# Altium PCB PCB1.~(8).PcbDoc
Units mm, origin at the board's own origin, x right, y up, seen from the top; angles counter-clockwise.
Board outline 200.03 x 149.86 mm, 2 copper layers (Top Layer, Bottom Layer); 48 components, 42 nets, 243 pads, 0 vias.
Unrouted connection lines stored in the file: 177.
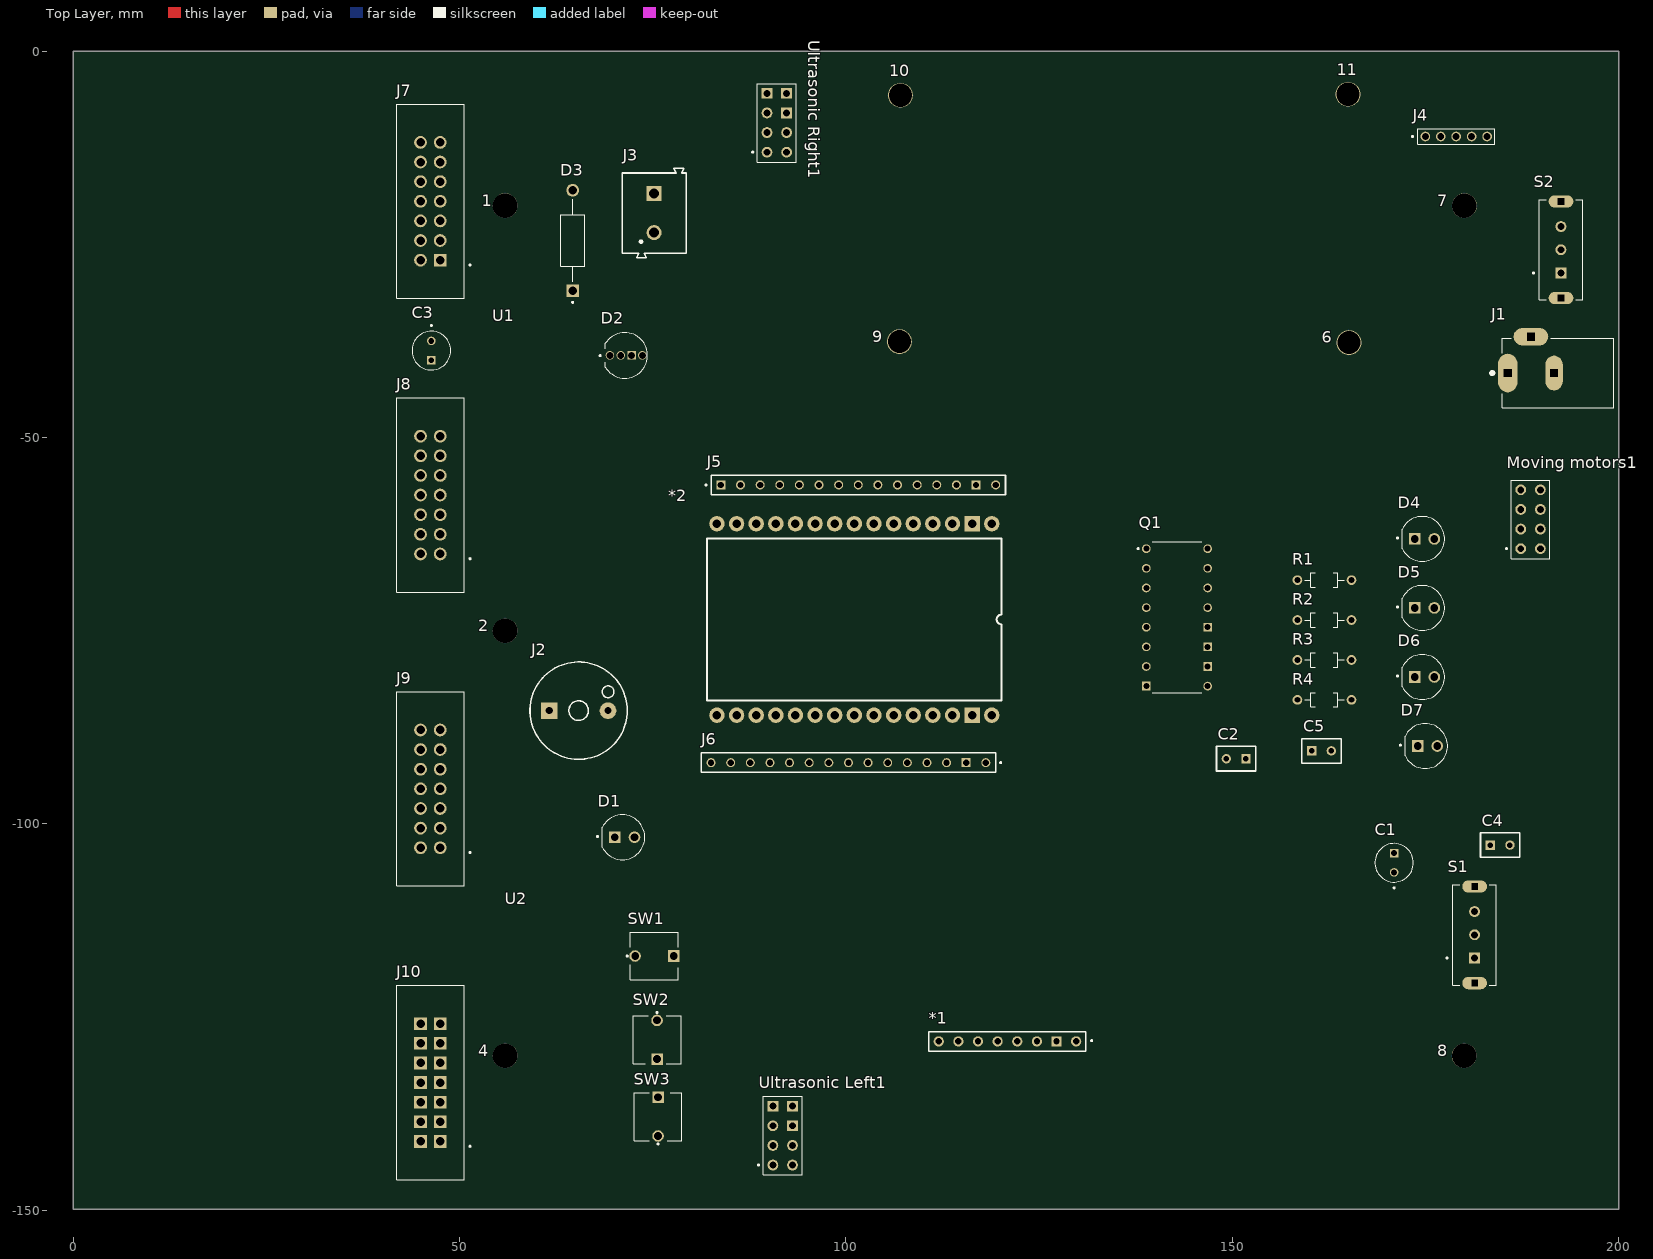
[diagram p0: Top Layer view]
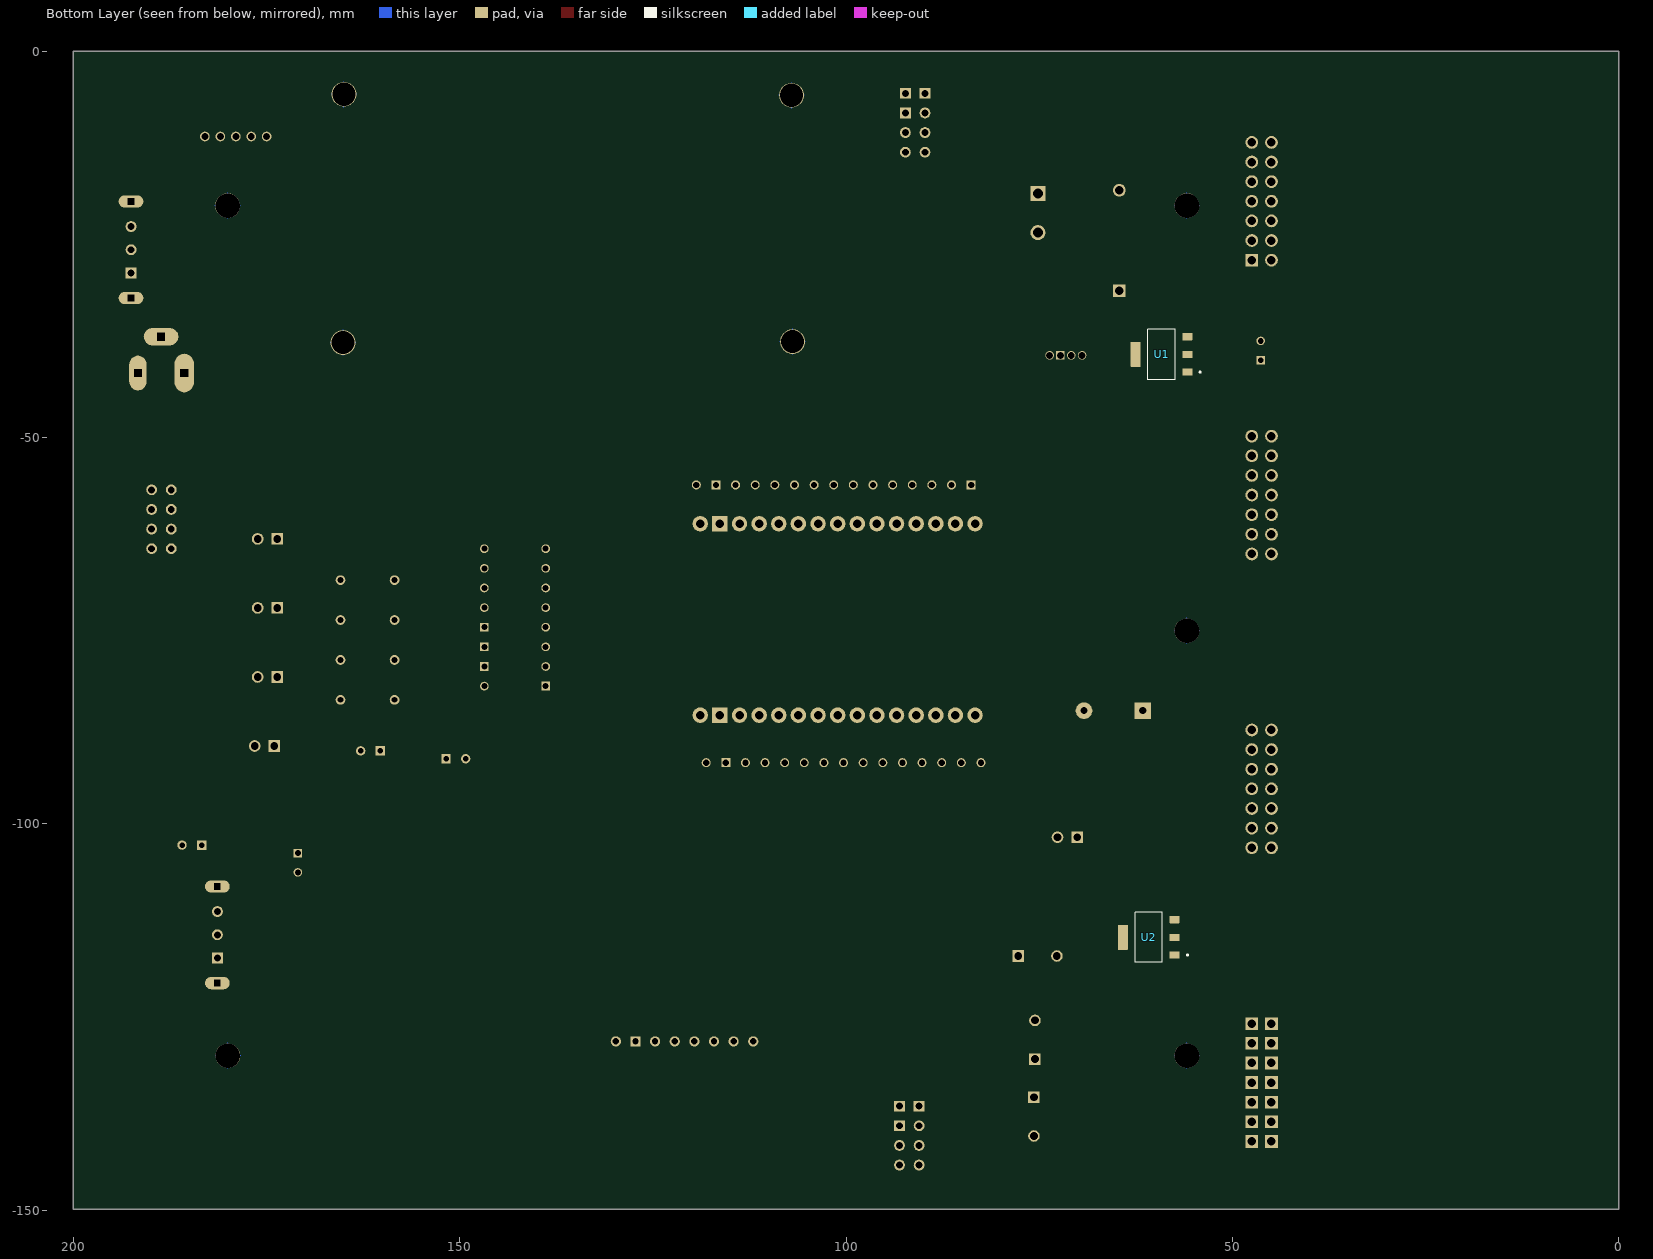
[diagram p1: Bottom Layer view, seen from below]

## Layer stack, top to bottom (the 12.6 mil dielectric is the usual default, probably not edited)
Top Solder: solder mask 0.0102, Solder Resist, Dk 3.5
Top Layer: signal copper 0.0356
Dielectric 1: dielectric 0.32, FR-4, Dk 4.8
Bottom Layer: signal copper 0.0356
Bottom Solder: solder mask 0.0102, Solder Resist, Dk 3.5

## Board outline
0,-149.86 200.025,-149.86 200.025,0 0,0

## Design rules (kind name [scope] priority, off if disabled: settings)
Clearance [All] p1: gap=0.254 ignorepadtopadclearanceinfootprint=FALSE except(0: Arc-Hole Track-Hole SMDPad-Hole THPad-Hole Via-Hole Fill-Hole Poly-Hole Region-Hole Text-Hole)
PolygonConnect [All] p1: connectstyle=Relief reliefconductorwidth=0.254 reliefentries=4 polygonreliefangle="90 Angle" airgapwidth=0.254
RoutingLayers [All] p1: top layer_v5=FALSE bottom layer_v5=TRUE
RoutingVias [All] p1: holewidth=0.711 width=1.27 viastyle="Through Hole" minholewidth=0.711 minwidth=1.27 maxholewidth=0.711 maxwidth=1.27
SolderMaskExpansion [All] p1: expansion=0.102 istentingtop=FALSE
Width [All] p1: maxlimit=0.7 minlimit=0.254 preferedwidth=0.5
29 further rules are at their usual default settings.

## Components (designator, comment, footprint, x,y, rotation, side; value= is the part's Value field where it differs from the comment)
1 "Mounting Hole" PCBComponent_1#1 55.9,-20 r0 top
2 "Mounting Hole" PCBComponent_1#1 55.9,-75 r0 top
4 "Mounting Hole" PCBComponent_1#1 55.9,-130 r0 top
6 "Mounting Hole" PCBComponent_1#2 165.1,-37.719 r90 top
7 "Mounting Hole" PCBComponent_1#1 180.025,-20 r90 top
8 "Mounting Hole" PCBComponent_1#1 180,-130 r0 top
9 "Mounting Hole" PCBComponent_1#2 106.934,-37.592 r90 top
10 "Mounting Hole" PCBComponent_1#2 107.061,-5.715 r0 top
11 "Mounting Hole" PCBComponent_1#2 164.973,-5.588 r0 top
*1 "MPU-6050" MPU-6050 131.318,-126.619 r270 top
*2 "ESP32DEVKITV1" ESP32DEVKITV1 101.219,-72.841 r90 top
C1 "CAP  33UF 50V RADIAL" "CAP  33UF 50V RADIAL" 170.942,-105.029 r90 top
C2 "Ceramic Capacitor 100nF" C320C 143.495,-98.567 r180 top
C3 "CAP  33UF 50V RADIAL" "CAP  33UF 50V RADIAL" 46.355,-38.755 r270 top
C4 "Ceramic Capacitor 100nF" C320C 191.658,-95.743 r0 top
C5 "Ceramic Capacitor 100nF" C320C 168.544,-83.551 r0 top
D1 "LED 5mm" "LED 5mm" 71.374,-101.727 r0 top
D2 "common cathode" "LED RGB 5mm" 71.374,-39.37 r0 top
D3 "RL207" DIOAD1300W80L670D310 64.643,-24.511 r90 top
D4 "LED 5mm" "LED 5mm" 174.879,-63.119 r0 top
D5 "LED 5mm" "LED 5mm" 174.879,-72.051 r0 top
D6 "LED 5mm" "LED 5mm" 174.879,-80.984 r0 top
D7 "LED 5mm" "LED 5mm" 175.26,-89.916 r0 top
J1 "DC Power Jack Female Socket" "DC Power Jack Female Socket" 185.643,-41.656 r0 top
J2 "WST-1205S" WST-1205S 65.415,-85.344 r0 top
J3 "From Buck" 691213510002 75.184,-20.955 r90 top
J4 "Pin hreader 5 pins" "Pin hreader 5 pins" 174.975,-11.049 r0 top
J5 "TS-115-T-A-1" SAMTEC_TS-115-T-A-1#1 101.6,-56.134 r0 top
J6 "TS-115-T-A-1" SAMTEC_TS-115-T-A-1#2 100.33,-92.075 r180 top
J7 "12v pin headers block" AMPHENOL_52601-S14-4LF#1 46.228,-19.431 r90 top
J8 "5v pin headers block" AMPHENOL_52601-S14-4LF#2 46.228,-57.446 r90 top
J9 "3.3v pin headers block" AMPHENOL_52601-S14-4LF#2 46.228,-95.462 r90 top
J10 "GND pin headers block" AMPHENOL_52601-S14-4LF#3 46.228,-133.477 r90 top
"Moving motors1" "Pin header female block 8 pin" "Pin header female block 8 pin"#1 188.595,-60.579 r90 top
Q1 "ULN2003AN" DIP794W45P254L1969H508Q16 142.842,-73.279 r0 top
R1 "Resistor" RESAD700W45L350D185 161.925,-68.453 r180 top
R2 "Resistor" RESAD700W45L350D185 161.925,-73.618 r180 top
R3 "Resistor" RESAD700W45L350D185 161.925,-78.782 r180 top
R4 "Resistor" RESAD700W45L350D185 161.925,-83.947 r180 top
S1 "slide switch (5v,3.3v)" "Slide switch" 181.356,-114.348 r90 top
S2 "Slide switch" "Slide switch" 192.532,-25.702 r90 top
SW1 "FSM8JRT" TE_FSM8JRT 72.72,-117.094 r0 top
SW2 "FSM8JRT" TE_FSM8JRT 75.565,-125.425 r270 top
SW3 "FSM8JRT" TE_FSM8JRT 75.692,-140.386 r90 top
U1 "AMS1117-5.0" SOT229P700X180-4N 59.182,-39.243 r0 bottom
U2 "AMS1117-3.3" SOT229P700X180-4N 60.833,-114.681 r0 bottom
"Ultrasonic Left1" "Pin header female block 8 pin" "Pin header female block 8 pin"#2 91.821,-140.335 r90 top
"Ultrasonic Right1" "Pin header female block 8 pin" "Pin header female block 8 pin"#2 91.059,-9.271 r90 top

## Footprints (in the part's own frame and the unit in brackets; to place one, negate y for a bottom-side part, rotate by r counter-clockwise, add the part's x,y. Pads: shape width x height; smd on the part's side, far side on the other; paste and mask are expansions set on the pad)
691213510002 [mm]
  round 1.95 hole 1.3: 1(-2.54,0)
  rect 1.95x1.95 hole 1.3: 2(2.54,0)
  silkscreen extent -5.78,-4.15 5.78,4.15, body extent -5.68,-3.94 5.68,4.16, height 10
AMPHENOL_52601-S14-4LF#1 [mm]
  rect 1.65x1.65 hole 1.1: 1(-7.62,-1.27)
  round 1.65 hole 1.1: 2(-7.62,1.27) 3(-5.08,-1.27) 4(-5.08,1.27) 5(-2.54,-1.27) 6(-2.54,1.27) 7(0,-1.27) 8(0,1.27) 9(2.54,-1.27) 10(2.54,1.27) 11(5.08,-1.27) 12(5.08,1.27) 13(7.62,-1.27) 14(7.62,1.27)
  silkscreen extent -12.57,-5.23 12.57,4.38, body extent -12.57,-4.38 12.57,4.38, height 9.53
AMPHENOL_52601-S14-4LF#2 [mm]
  round 1.65 hole 1.1: 1(-7.62,-1.27) 2(-7.62,1.27) 3(-5.08,-1.27) 4(-5.08,1.27) 5(-2.54,-1.27) 6(-2.54,1.27) 7(0,-1.27) 8(0,1.27) 9(2.54,-1.27) 10(2.54,1.27) 11(5.08,-1.27) 12(5.08,1.27) 13(7.62,-1.27) 14(7.62,1.27)
  silkscreen extent -12.57,-5.23 12.57,4.38, body extent -12.57,-4.38 12.57,4.38, height 9.53
AMPHENOL_52601-S14-4LF#3 [mm]
  rect 1.65x1.65 hole 1.1: 1(-7.62,-1.27) 2(-7.62,1.27) 3(-5.08,-1.27) 4(-5.08,1.27) 5(-2.54,-1.27) 6(-2.54,1.27) 7(0,-1.27) 8(0,1.27) 9(2.54,-1.27) 10(2.54,1.27) 11(5.08,-1.27) 12(5.08,1.27) 13(7.62,-1.27) 14(7.62,1.27)
  silkscreen extent -12.57,-5.23 12.57,4.38, body extent -12.57,-4.38 12.57,4.38, height 9.53
C320C [mm]
  rect 1.21x1.21 hole 0.71: 1(-8.27,-7)
  round 1.21 hole 0.71: 2(-5.73,-7)
  silkscreen extent -9.54,-8.59 -4.46,-5.41, body extent -9.53,-8.57 -4.45,-5.4, height 7.1
"CAP  33UF 50V RADIAL" [mm]
  rect 1.1x1.1 hole 0.75: N(1.25,0)
  round 1.1 hole 0.75: P(-1.25,0)
  silkscreen extent -3.35,-2.5 2.5,2.5, body extent -2.49,-2.5 2.5,2.5, height 11
"DC Power Jack Female Socket" [mm]
  oval 2.5x5 hole 1 square: 1(0,0)
  oval 2.25x4.5 hole 1 square: 2(6,0)
  oval 4.5x2.25 hole 1 square: 3(3,4.7)
  silkscreen extent -2.2,-4.5 13.7,4.5, body extent -0.7,-4.5 13.7,4.9, height 11
DIOAD1300W80L670D310 [mm]
  round 1.65 hole 1.1: A(6.5,0)
  rect 1.65x1.65 hole 1.1: C(-6.5,0)
  silkscreen extent -8.1,-1.55 5.32,1.55, body extent -6.9,-1.95 6.9,1.65, height 3.6
DIP794W45P254L1969H508Q16 [mm]
  round 1.13 hole 0.78: 1(-3.97,8.89) 2(-3.97,6.35) 3(-3.97,3.81) 4(-3.97,1.27) 5(-3.97,-1.27) 6(-3.97,-3.81) 7(-3.97,-6.35) 9(3.97,-8.89) 13(3.97,1.27) 14(3.97,3.81) 15(3.97,6.35) 16(3.97,8.89)
  rect 1.13x1.13 hole 0.78: 8(-3.97,-8.89) 10(3.97,-6.35) 11(3.97,-3.81) 12(3.97,-1.27)
  silkscreen extent -5.13,-9.77 3.17,9.77, body extent -3.95,-10.54 3.95,10.79, height 5.08
ESP32DEVKITV1 [mm]
  round 2 hole 1.1: 1(11.684,-17.653) 3(11.684,-12.573) 4(11.684,-10.033) 5(11.684,-7.493) 6(11.684,-4.953) 7(11.684,-2.413) 8(11.684,0.127) 9(11.684,2.667) 10(11.684,5.207) 11(11.684,7.747) 12(11.684,10.287) 13(11.684,12.827) 14(11.684,15.367) 15(11.684,17.907) 16(-13.086,17.907) 17(-13.086,15.367) 18(-13.086,12.827) 19(-13.086,10.287) 20(-13.086,7.747) 21(-13.086,5.207) 22(-13.086,2.667) 23(-13.086,0.127) 24(-13.086,-2.413) 25(-13.086,-4.953) 26(-13.086,-7.493) 27(-13.086,-10.033) 28(-13.086,-12.573) 30(-13.086,-17.653)
  rect 2x2 hole 1.1: 2(11.684,-15.113) 29(-13.086,-15.113)
  silkscreen extent -11.2,-18.92 9.79,19.18, body extent -15.13,-28.49 13.86,24.48, height 8.36
"LED 5mm" [mm]
  round 1.508 hole 1: A(1.27,0)
  rect 1.508x1.508 hole 1: C(-1.27,0)
  silkscreen extent -3.6,-2.9 2.6,2.9, body extent -2.88,-2.9 2.51,2.9, height 12.1
"LED RGB 5mm" [mm]
  round 1.1 hole 0.9: 1(-1.905,0) 2(-0.508,0) 4(2.286,0)
  rect 1.1x1.1 hole 0.9: 3(0.889,0)
  silkscreen extent -3.27,-2.95 2.95,2.95, body extent -2.47,-3.05 2.98,2.84, height 9.6
MPU-6050 [mil]
  round 52 hole 32: 01(60,-60) 03(60,-260) 04(60,-360) 05(60,-460) 06(60,-560) 07(60,-660) 08(60,-760)
  rect 52x52 hole 32: 02(60,-160)
  silkscreen extent 10,-810 110,23, body extent 15,-811 615,-9, height 62
PCBComponent_1#1 [mm]
  round 3.2 hole 3.2: ""(0,0)
  Bottom Layer lines w0.15: -1.651,0 1.649,0 ; 0,-1.651 0,1.649
PCBComponent_1#2 [mm]
  round 3.2 hole 3: ""(0,0)
  Bottom Layer lines w0.15: 0,1.649 0,-1.651 ; -1.651,0 1.649,0
"Pin header female block 8 pin"#1 [mm]
  round 1.398 hole 0.89: 1(-3.81,1.27) 2(-1.27,1.27) 3(1.27,1.27) 4(3.81,1.27) 5(-3.81,-1.27) 6(-1.27,-1.27) 7(1.27,-1.27) 8(3.81,-1.27)
  silkscreen extent -5.08,-2.52 5.08,3.21, body extent -5.08,-2.51 5.08,2.51, height 6.22
"Pin header female block 8 pin"#2 [mm]
  round 1.398 hole 0.89: 1(-3.81,1.27) 2(-1.27,1.27) 3(1.27,1.27) 5(-3.81,-1.27) 6(-1.27,-1.27)
  rect 1.398x1.398 hole 0.89: 4(3.81,1.27) 7(1.27,-1.27) 8(3.81,-1.27)
  silkscreen extent -5.08,-2.52 5.08,3.21, body extent -5.08,-2.51 5.08,2.51, height 6.22
"Pin hreader 5 pins" [mm]
  round 1.25 hole 0.9: 1(0,0) 2(2,0) 3(4,0) 4(6,0) 5(8,0)
  silkscreen extent -1.75,-1 9,1, body extent -1,-1 9,1, height 5.65
RESAD700W45L350D185 [mm]
  round 1.258 hole 0.75: 1(-3.5,0) 2(3.5,0)
  silkscreen extent -2.55,-0.93 2.55,0.93, body extent -3.72,-1.05 3.72,0.8, height 1.85
SAMTEC_TS-115-T-A-1#1 [mil]
  rect 45.78x45.78 hole 32: 01(-700,0) 14(600,0)
  round 45.78 hole 32: 02(-600,0) 03(-500,0) 04(-400,0) 05(-300,0) 06(-200,0) 07(-100,0) 08(0,0) 09(100,0) 10(200,0) 11(300,0) 12(400,0) 13(500,0) 15(700,0)
  silkscreen extent -780,-50 750,50, body extent -754,-50 754,50, height 326
SAMTEC_TS-115-T-A-1#2 [mil]
  round 45.78 hole 32: 01(-700,0) 03(-500,0) 04(-400,0) 05(-300,0) 06(-200,0) 07(-100,0) 08(0,0) 09(100,0) 10(200,0) 11(300,0) 12(400,0) 13(500,0) 14(600,0) 15(700,0)
  rect 45.78x45.78 hole 32: 02(-600,0)
  silkscreen extent -780,-50 750,50, body extent -754,-50 754,50, height 326
"Slide switch" [mm]
  rect 1.408x1.408 hole 0.9: 1(-3,0)
  round 1.408 hole 0.9: 2(0,0) 3(3,0)
  oval 1.6x3.2 hole 0.8 square: SH1(-6.25,0) SH2(6.25,0)
  silkscreen extent -6.5,-2.8 6.5,3.66, body extent -6.5,-5.8 6.5,2.8, height 6
SOT229P700X180-4N [mm]
  rrect15% 1.31x0.93 smd: 1(-3.345,2.29) 2(-3.345,0) 3(-3.345,-2.29)
  rrect15% 1.31x3.24 smd: 4(3.345,0)
  silkscreen extent -5.1,-3.25 1.75,3.25, body extent -3.5,-3.25 3.5,3.25, height 1.8
TE_FSM8JRT [mil]
  round 59 hole 39: 1(0,0)
  rect 59x59 hole 39: 2(197,0)
  silkscreen extent -44,-122 220,122, body extent -22,-122 222,122, height 372
WST-1205S [mil]
  rect 85x85 hole 36: NEG(-149.61,0)
  round 85 hole 36: POS(149.61,0)
  silkscreen extent -248,-248 248,248, body extent -236,-236 236,236, height 394

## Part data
C1 C3: "NHG-A", Package=None
C2 C4 C5: "0.1ÂµF Â±20% 50V Ceramic Capacitor Z5U Radial", Package="Radial KEMET"
D1 D4 D5 D6 D7: "Red 623nm LED Indication - Discrete 1.9V Radial", Package=None
D2: library part "LED RGB 5mm", Package=None
D3: "Semiconductors and Actives, Power Diodes, Discretes (diodes, transistors, thyristors ...), Diodes", Package=None
J1: "2.0 mm Center Pin, 2.5 A, Right Angle, Through Hole, Dc Power Jack Connector", Package=None
J2: "BUZZER 2.3KHZ 4-6VDC", Package=None
J3: library part "Terminal Block", "2 Position Wire to Board Terminal Block Horizontal with Board 0.200 (5.08mm) Through Hole", Package=None
J4 J5 J6 "Moving motors1" Q1 S2 U1 U2 "Ultrasonic Left1" "Ultrasonic Right1": Package=None
J7 J8 J9 J10: library part 52601-S14-4LF, Package=None
R1 R2 R3 R4: "CFR16 5% 10K", Package=None
S1: library part "Slide switch", Package=None
SW1 SW2 SW3: "Tactile Switches PUSHBUTTON SWITCH TACT", Package=None

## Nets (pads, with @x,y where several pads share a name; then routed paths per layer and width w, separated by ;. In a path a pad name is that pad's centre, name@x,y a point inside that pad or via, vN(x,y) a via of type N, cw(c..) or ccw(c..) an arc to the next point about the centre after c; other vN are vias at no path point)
3.3V: *1.01 *2.1 C2.2 J5.15 J9.1 J9.2 J9.3 J9.4 J9.5 J9.6 J9.7 J9.8 J9.9 J9.10 J9.11 J9.12 J9.13 J9.14 U2.2
+5: "Ultrasonic Left1.1" "Ultrasonic Left1.5" "Ultrasonic Right1.1" "Ultrasonic Right1.5" C1.P J8.1 J8.2 J8.3 J8.4 J8.5 J8.6 J8.7 J8.8 J8.9 J8.10 J8.11 J8.12 J8.13 J8.14 S1.1 S1.2 S2.3 U1.2
+12: D3.A J1.1 J3.1 J7.1 J7.2 J7.3 J7.4 J7.5 J7.6 J7.7 J7.8 J7.9 J7.10 J7.11 J7.12 J7.13 J7.14 S2.1
GND: "Ultrasonic Left1.4" "Ultrasonic Left1.7" "Ultrasonic Left1.8" "Ultrasonic Right1.4" "Ultrasonic Right1.7" "Ultrasonic Right1.8" *1.02 *2.2 *2.29 C1.N C2.1 C3.N C4.1 C5.1 D1.C D2.3 J1.2 J1.3 J2.NEG J3.2 J5.14 J6.02 J10.1 J10.2 J10.3 J10.4 J10.5 J10.6 J10.7 J10.8 J10.9 J10.10 J10.11 J10.12 J10.13 J10.14 Q1.8 Q1.10 Q1.11 Q1.12 SW1.2 SW2.2 SW3.2 U1.1 U2.1
Net*1_03: *1.03 *2.14 J5.02
Net*1_04: *1.04 *2.11 J5.05
Net*2_3: *2.3 J5.13 Q1.4
Net*2_4: *2.4 D2.2 J5.12
Net*2_5: "Moving motors1.8" *2.5 J5.11
Net*2_6: "Moving motors1.7" *2.6 J5.10
Net*2_7: "Moving motors1.6" *2.7 J5.09
Net*2_8: "Ultrasonic Right1.6" *2.8 J5.08
Net*2_9: "Ultrasonic Right1.3" *2.9 J5.07
Net*2_10: "Ultrasonic Right1.2" *2.10 J5.06
Net*2_12: *2.12 D2.4 J5.04
Net*2_13: *2.13 D2.1 J5.03
Net*2_15: *2.15 J2.POS J5.01
Net*2_16: *2.16 J6.15
Net*2_17: *2.17 J6.14 SW1.1
Net*2_18: *2.18 J6.13 SW2.1
Net*2_19: *2.19 J6.12 SW3.1
Net*2_20: "Ultrasonic Left1.3" *2.20 J6.11
Net*2_21: "Ultrasonic Left1.2" *2.21 J6.10
Net*2_22: "Ultrasonic Left1.6" *2.22 J6.09
Net*2_23: "Moving motors1.1" *2.23 J6.08
Net*2_24: "Moving motors1.3" *2.24 J6.07
Net*2_25: "Moving motors1.2" *2.25 J6.06
Net*2_26: *2.26 J6.05 Q1.1
Net*2_27: *2.27 J6.04 Q1.2
Net*2_28: *2.28 J6.03 Q1.3
Net*2_30: *2.30 J6.01
NetC3_P: C3.P D3.C U1.3
NetC4_2: C4.2 D1.A S1.3 U2.3
NetC5_2: C5.2 D4.A D5.A D6.A D7.A J4.1 Q1.9 S2.2
NetD4_C: D4.C R1.1
NetD5_C: D5.C R2.1
NetD6_C: D6.C R3.1
NetD7_C: D7.C R4.1
NetJ4_2: J4.2 Q1.16 R1.2
NetJ4_3: J4.3 Q1.15 R2.2
NetJ4_4: J4.4 Q1.14 R3.2
NetJ4_5: J4.5 Q1.13 R4.2
pads on no net: 1. 2. 4. 6. 7. 8. 9. 10. 11. "Moving motors1.4" "Moving motors1.5" *1.05 *1.06 *1.07 *1.08 Q1.5 Q1.6 Q1.7 S1.SH1 S1.SH2 S2.SH1 S2.SH2 U1.4 U2.4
